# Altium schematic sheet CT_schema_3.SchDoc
size 235 x 277 mm
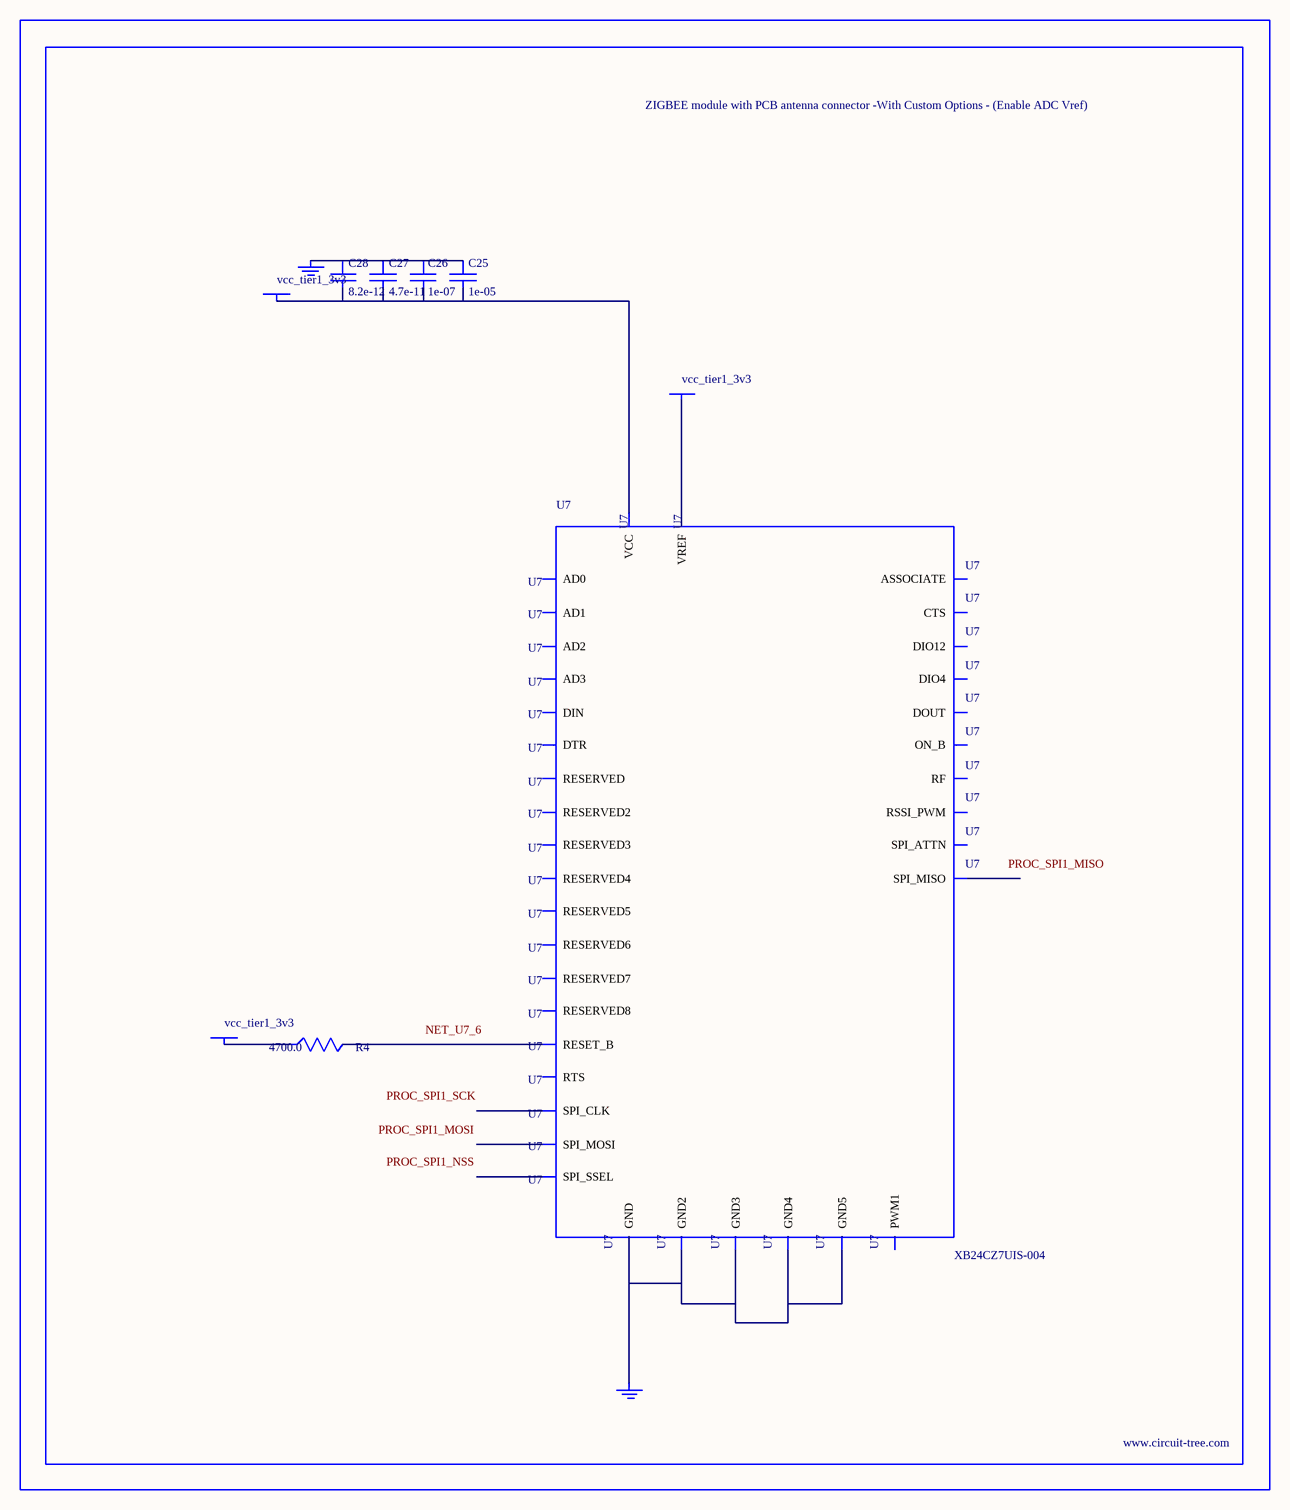
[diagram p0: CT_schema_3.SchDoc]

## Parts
BORDER2  (no value)
C25  1e-05  [C0805]
C26  1e-07  [C0402]
C27  4.7e-11  [C0402]
C28  8.2e-12  [C0603]
GND_INSTANCE_2_0  (no value)
GND_INSTANCE_2_1  (no value)
POWER_INSTANCE_2_0  vcc_tier1_3v3
POWER_INSTANCE_2_1  vcc_tier1_3v3
POWER_INSTANCE_2_2  vcc_tier1_3v3
R4  4700.0  [R0603]
U7  XB24CZ7UIS-004  [XB24CZ7UIS-004]

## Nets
NetC25_1: C25.1 C26.1 C27.1 C28.1 GND_INSTANCE_2_0.0(GND)
NetC25_2: C25.2 C26.2 C27.2 C28.2 POWER_INSTANCE_2_0.0(PWR) U7.2(VCC)
NetGND_INSTANCE_2_1_0: GND_INSTANCE_2_1.0(GND) U7.1(GND) U7.11(GND2) U7.13(GND3) U7.22(GND4) U7.35(GND5)
NetPOWER_INSTANCE_2_1_0: POWER_INSTANCE_2_1.0(PWR) R4.1
NetPOWER_INSTANCE_2_2_0: POWER_INSTANCE_2_2.0(PWR) U7.27(VREF)
NetR4_2: R4.2 U7.6(RESET_B)

Not connected (* = marked no-connect by the designer): U7 3(DOUT) 4(DIN) 5(DIO12) 7(RSSI_PWM) 8(PWM1) 9(RESERVED) 10(DTR) 12(SPI_ATTN) 14(SPI_CLK) 15(SPI_SSEL) 16(SPI_MOSI) 17(SPI_MISO) 18(RESERVED2) 19(RESERVED3) 20(RESERVED4) 21(RESERVED5) 23(RESERVED6) 24(DIO4) 25(CTS) 26(ON_B) 28(ASSOCIATE) 29(RTS) 30(AD3) 31(AD2) 32(AD1) 33(AD0) 34(RESERVED7) 36(RF) 37(RESERVED8)

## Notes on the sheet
- Labels drawn without touching a wire or pin: NET_U7_6, PROC_SPI1_MISO, PROC_SPI1_MOSI, PROC_SPI1_NSS, PROC_SPI1_SCK

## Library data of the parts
BORDER2 = BORDER_PAGE2
C25 = C0805C106K8RACTU
C26 = C0402C104K3RACTU
C27 = C0402C470K3RAC
C28 = 06035J8R2BBTTR
GND_INSTANCE_2_0 GND_INSTANCE_2_1 = GND
POWER_INSTANCE_2_0-POWER_INSTANCE_2_2 = PWR
R4 = RC0603JR-074K7L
